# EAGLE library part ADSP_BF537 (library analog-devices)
ADSP-BF534-BSDL_br.txt.bsdl Auto generated by make-symbol-device-package-bsdl.ulp Rev. 8 Source: http://www.analog.com/UploadedFiles/Data_Sheets/90140778ADSP_BF536_7_prd.pdf Source2: BSDL_br.txt as Email: <adi-germany@analog.com>
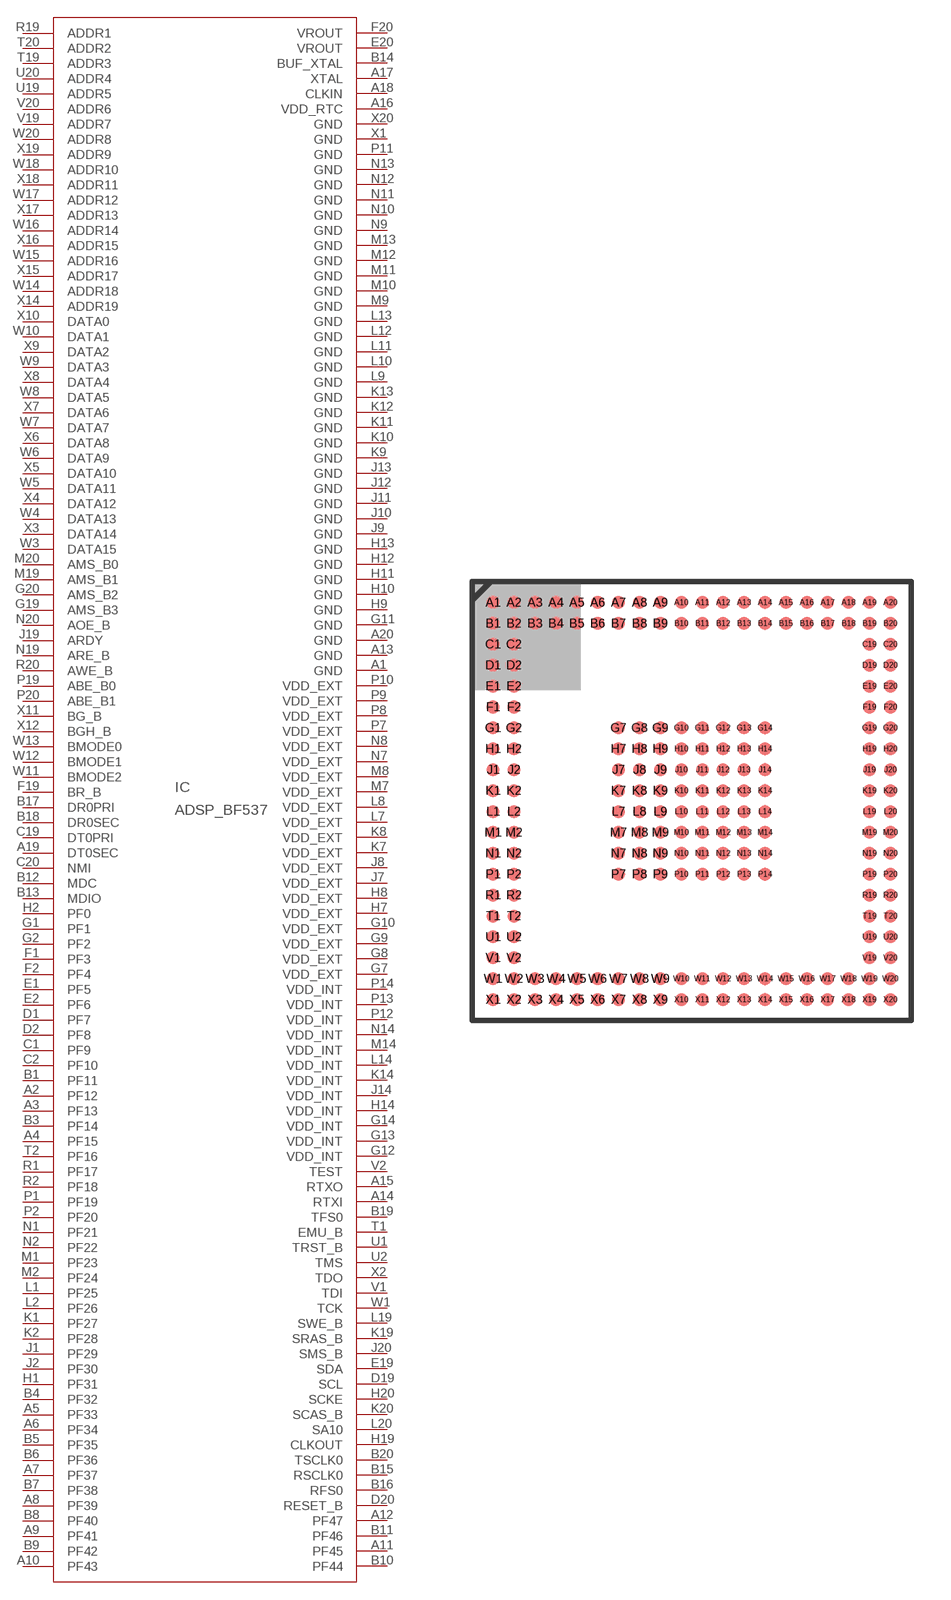
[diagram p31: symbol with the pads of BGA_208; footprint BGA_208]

Designator prefix IC

## ADSP_BF537 (MPN: ADSP-BF537BBCZ-5B; OC_FARNELL: 1776215; OC_NEWARK: 31M8122)  [BGA_208]
A1  GND  pwr
A2  PF12
A3  PF13
A4  PF15
A5  PF33
A6  PF34
A7  PF37
A8  PF39
A9  PF41
A10  PF43
A11  PF45
A12  PF47
A13  GND  pwr
A14  RTXI  pwr
A15  RTXO  pwr
A16  VDD_RTC  pwr
A17  XTAL  pwr
A18  CLKIN  pwr
A19  DT0SEC
A20  GND  pwr
B1  PF11
B3  PF14
B4  PF32
B5  PF35
B6  PF36
B7  PF38
B8  PF40
B9  PF42
B10  PF44
B11  PF46
B12  MDC
B13  MDIO
B14  BUF_XTAL  pwr
B15  RSCLK0
B16  RFS0
B17  DR0PRI
B18  DR0SEC
B19  TFS0
B20  TSCLK0
C1  PF9
C2  PF10
C19  DT0PRI
C20  NMI  in
D1  PF7
D2  PF8
D19  SCL
D20  RESET_B  in
E1  PF5
E2  PF6
E19  SDA
E20  VROUT  pwr
F1  PF3
F2  PF4
F19  BR_B  in
F20  VROUT  pwr
G1  PF1
G2  PF2
G7  VDD_EXT  pwr
G8  VDD_EXT  pwr
G9  VDD_EXT  pwr
G10  VDD_EXT  pwr
G11  GND  pwr
G12  VDD_INT  pwr
G13  VDD_INT  pwr
G14  VDD_INT  pwr
G19  AMS_B3  out
G20  AMS_B2  out
H1  PF31
H2  PF0
H7  VDD_EXT  pwr
H8  VDD_EXT  pwr
H9  GND  pwr
H10  GND  pwr
H11  GND  pwr
H12  GND  pwr
H13  GND  pwr
H14  VDD_INT  pwr
H19  CLKOUT  out
H20  SCKE  out
J1  PF29
J2  PF30
J7  VDD_EXT  pwr
J8  VDD_EXT  pwr
J9  GND  pwr
J10  GND  pwr
J11  GND  pwr
J12  GND  pwr
J13  GND  pwr
J14  VDD_INT  pwr
J19  ARDY  in
J20  SMS_B  out
K1  PF27
K2  PF28
K7  VDD_EXT  pwr
K8  VDD_EXT  pwr
K9  GND  pwr
K10  GND  pwr
K11  GND  pwr
K12  GND  pwr
K13  GND  pwr
K14  VDD_INT  pwr
K19  SRAS_B  out
K20  SCAS_B  out
L1  PF25
L2  PF26
L7  VDD_EXT  pwr
L8  VDD_EXT  pwr
L9  GND  pwr
L10  GND  pwr
L11  GND  pwr
L12  GND  pwr
L13  GND  pwr
L14  VDD_INT  pwr
L19  SWE_B  out
L20  SA10  out
M1  PF23
M2  PF24
M7  VDD_EXT  pwr
M8  VDD_EXT  pwr
M9  GND  pwr
M10  GND  pwr
M11  GND  pwr
M12  GND  pwr
M13  GND  pwr
M14  VDD_INT  pwr
M19  AMS_B1  out
M20  AMS_B0  out
N1  PF21
N2  PF22
N7  VDD_EXT  pwr
N8  VDD_EXT  pwr
N9  GND  pwr
N10  GND  pwr
N11  GND  pwr
N12  GND  pwr
N13  GND  pwr
N14  VDD_INT  pwr
N19  ARE_B  out
N20  AOE_B  out
P1  PF19
P2  PF20
P7  VDD_EXT  pwr
P8  VDD_EXT  pwr
P9  VDD_EXT  pwr
P10  VDD_EXT  pwr
P11  GND  pwr
P12  VDD_INT  pwr
P13  VDD_INT  pwr
P14  VDD_INT  pwr
P19  ABE_B0  out
P20  ABE_B1  out
R1  PF17
R2  PF18
R19  ADDR1  out
R20  AWE_B  out
T1  EMU_B  pwr
T2  PF16
T19  ADDR3  out
T20  ADDR2  out
U1  TRST_B  in
U2  TMS  in
U19  ADDR5  out
U20  ADDR4  out
V1  TDI  in
V2  TEST  in
V19  ADDR7  out
V20  ADDR6  out
W1  TCK  in
W3  DATA15
W4  DATA13
W5  DATA11
W6  DATA9
W7  DATA7
W8  DATA5
W9  DATA3
W10  DATA1
W11  BMODE2  in
W12  BMODE1  in
W13  BMODE0  in
W14  ADDR18  out
W15  ADDR16  out
W16  ADDR14  out
W17  ADDR12  out
W18  ADDR10  out
W20  ADDR8  out
X1  GND  pwr
X2  TDO  out
X3  DATA14
X4  DATA12
X5  DATA10
X6  DATA8
X7  DATA6
X8  DATA4
X9  DATA2
X10  DATA0
X11  BG_B  hiz
X12  BGH_B  hiz
X14  ADDR19  out
X15  ADDR17  out
X16  ADDR15  out
X17  ADDR13  out
X18  ADDR11  out
X19  ADDR9  out
X20  GND  pwr

## Footprint BGA_208 (pad centres in mm)
208-Ball Sparse Mini-BGA Auto generated by make-symbol-device-package-bsdl.ulp Rev. 8 Source: http://www.analog.com/UploadedFiles/Data_Sheets/90140778ADSP_BF536_7_prd.pdf Source2: BSDL_br.txt as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
smd 0.5 x 0.5: A1 -7.6,7.6; A2 -6.8,7.6; A3 -6,7.6; A4 -5.2,7.6; A5 -4.4,7.6; A6 -3.6,7.6; A7 -2.8,7.6; A8 -2,7.6; A9 -1.2,7.6; A10 -0.4,7.6; A11 0.4,7.6; A12 1.2,7.6; A13 2,7.6; A14 2.8,7.6; A15 3.6,7.6; A16 4.4,7.6; A17 5.2,7.6; A18 6,7.6; A19 6.8,7.6; A20 7.6,7.6; B1 -7.6,6.8; B2 -6.8,6.8; B3 -6,6.8; B4 -5.2,6.8; B5 -4.4,6.8; B6 -3.6,6.8; B7 -2.8,6.8; B8 -2,6.8; B9 -1.2,6.8; B10 -0.4,6.8; B11 0.4,6.8; B12 1.2,6.8; B13 2,6.8; B14 2.8,6.8; B15 3.6,6.8; B16 4.4,6.8; B17 5.2,6.8; B18 6,6.8; B19 6.8,6.8; B20 7.6,6.8; C1 -7.6,6; C2 -6.8,6; C19 6.8,6; C20 7.6,6; D1 -7.6,5.2; D2 -6.8,5.2; D19 6.8,5.2; D20 7.6,5.2; E1 -7.6,4.4; E2 -6.8,4.4; E19 6.8,4.4; E20 7.6,4.4; F1 -7.6,3.6; F2 -6.8,3.6; F19 6.8,3.6; F20 7.6,3.6; G1 -7.6,2.8; G2 -6.8,2.8; G7 -2.8,2.8; G8 -2,2.8; G9 -1.2,2.8; G10 -0.4,2.8; G11 0.4,2.8; G12 1.2,2.8; G13 2,2.8; G14 2.8,2.8; G19 6.8,2.8; G20 7.6,2.8; H1 -7.6,2; H2 -6.8,2; H7 -2.8,2; H8 -2,2; H9 -1.2,2; H10 -0.4,2; H11 0.4,2; H12 1.2,2; H13 2,2; H14 2.8,2; H19 6.8,2; H20 7.6,2; J1 -7.6,1.2; J2 -6.8,1.2; J7 -2.8,1.2; J8 -2,1.2; J9 -1.2,1.2; J10 -0.4,1.2; J11 0.4,1.2; J12 1.2,1.2; J13 2,1.2; J14 2.8,1.2; J19 6.8,1.2; J20 7.6,1.2; K1 -7.6,0.4; K2 -6.8,0.4; K7 -2.8,0.4; K8 -2,0.4; K9 -1.2,0.4; K10 -0.4,0.4; K11 0.4,0.4; K12 1.2,0.4; K13 2,0.4; K14 2.8,0.4; K19 6.8,0.4; K20 7.6,0.4; L1 -7.6,-0.4; L2 -6.8,-0.4; L7 -2.8,-0.4; L8 -2,-0.4; L9 -1.2,-0.4; L10 -0.4,-0.4; L11 0.4,-0.4; L12 1.2,-0.4; L13 2,-0.4; L14 2.8,-0.4; L19 6.8,-0.4; L20 7.6,-0.4; M1 -7.6,-1.2; M2 -6.8,-1.2; M7 -2.8,-1.2; M8 -2,-1.2; M9 -1.2,-1.2; M10 -0.4,-1.2; M11 0.4,-1.2; M12 1.2,-1.2; M13 2,-1.2; M14 2.8,-1.2; M19 6.8,-1.2; M20 7.6,-1.2; N1 -7.6,-2; N2 -6.8,-2; N7 -2.8,-2; N8 -2,-2; N9 -1.2,-2; N10 -0.4,-2; N11 0.4,-2; N12 1.2,-2; N13 2,-2; N14 2.8,-2; N19 6.8,-2; N20 7.6,-2; P1 -7.6,-2.8; P2 -6.8,-2.8; P7 -2.8,-2.8; P8 -2,-2.8; P9 -1.2,-2.8; P10 -0.4,-2.8; P11 0.4,-2.8; P12 1.2,-2.8; P13 2,-2.8; P14 2.8,-2.8; P19 6.8,-2.8; P20 7.6,-2.8; R1 -7.6,-3.6; R2 -6.8,-3.6; R19 6.8,-3.6; R20 7.6,-3.6; T1 -7.6,-4.4; T2 -6.8,-4.4; T19 6.8,-4.4; T20 7.6,-4.4; U1 -7.6,-5.2; U2 -6.8,-5.2; U19 6.8,-5.2; U20 7.6,-5.2; V1 -7.6,-6; V2 -6.8,-6; V19 6.8,-6; V20 7.6,-6; W1 -7.6,-6.8; W2 -6.8,-6.8; W3 -6,-6.8; W4 -5.2,-6.8; W5 -4.4,-6.8; W6 -3.6,-6.8; W7 -2.8,-6.8; W8 -2,-6.8; W9 -1.2,-6.8; W10 -0.4,-6.8; W11 0.4,-6.8; W12 1.2,-6.8; W13 2,-6.8; W14 2.8,-6.8; W15 3.6,-6.8; W16 4.4,-6.8; W17 5.2,-6.8; W18 6,-6.8; W19 6.8,-6.8; W20 7.6,-6.8; X1 -7.6,-7.6; X2 -6.8,-7.6; X3 -6,-7.6; X4 -5.2,-7.6; X5 -4.4,-7.6; X6 -3.6,-7.6; X7 -2.8,-7.6; X8 -2,-7.6; X9 -1.2,-7.6; X10 -0.4,-7.6; X11 0.4,-7.6; X12 1.2,-7.6; X13 2,-7.6; X14 2.8,-7.6; X15 3.6,-7.6; X16 4.4,-7.6; X17 5.2,-7.6; X18 6,-7.6; X19 6.8,-7.6; X20 7.6,-7.6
